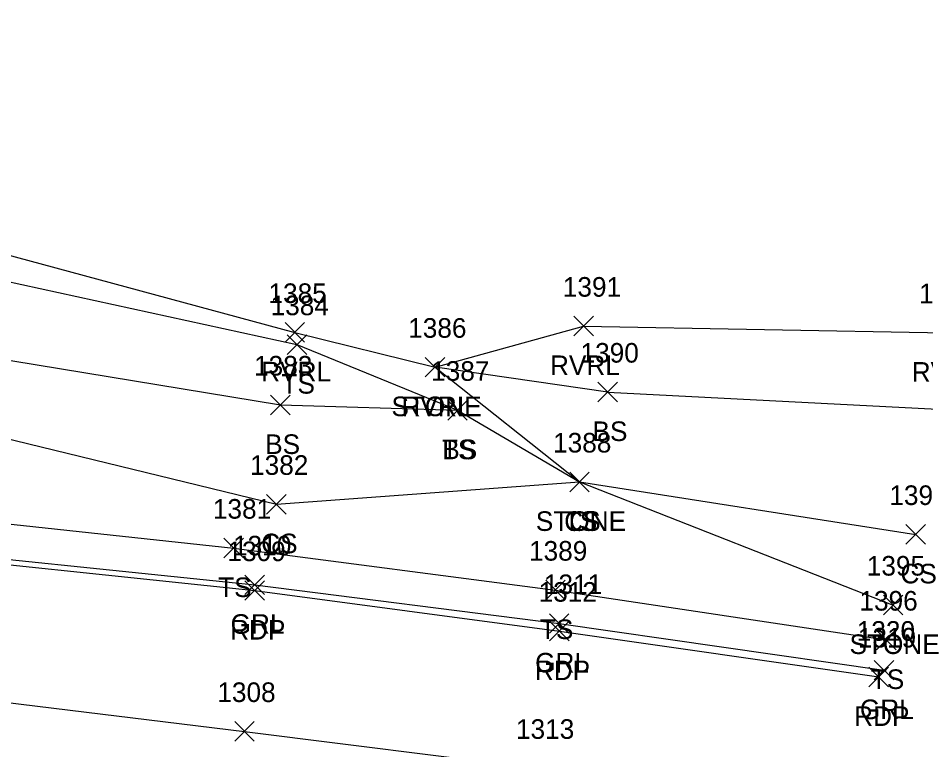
# Model space of a CAD drawing. Extents: x 1514253 to 1516033, y 782541 to 785002.
# Drawn here: x 1515367.9 to 1515460.6, y 782687.6 to 782762.3 of the extents above; entities that cross this region are included whole.
import ezdxf

# ---------------------------------------------------------------- set-up
doc = ezdxf.new("R2010")
doc.units = 0
for name, color, linetype in [('L_A', 7, 'Continuous'), ('L_I', 7, 'Continuous'), ('L_TIC', 7, 'Continuous'), ('LASF', 7, 'Continuous'), ('LAWE', 7, 'Continuous'), ('LELB', 7, 'Continuous'), ('P_A', 7, 'Continuous'), ('P_I', 7, 'Continuous'), ('P_TIC', 7, 'Continuous'), ('PET', 7, 'Continuous'), ('PRC', 7, 'Continuous'), ('R_A', 7, 'Continuous'), ('R_I', 7, 'Continuous'), ('R_TIC', 7, 'Continuous'), ('RGR', 7, 'Continuous')]:
    doc.layers.add(name, color=color, linetype=linetype)

msp = doc.modelspace()

# ---------------------------------------------------------------- linework, layer by layer
at = {"layer": 'L_TIC'}
for points in [[(1515395.169, 782729.21), (1515397.169, 782731.21)], [(1515397.169, 782729.21), (1515395.169, 782731.21)], [(1515424.647, 782729.856), (1515426.647, 782731.856)], [(1515426.647, 782729.856), (1515424.647, 782731.856)], [(1515395.387, 782727.965), (1515397.387, 782729.965)], [(1515397.387, 782727.965), (1515395.387, 782729.965)], [(1515409.484, 782725.666), (1515411.484, 782727.666)], [(1515411.484, 782725.666), (1515409.484, 782727.666)], [(1515409.484, 782725.666), (1515411.484, 782727.666)], [(1515411.484, 782725.666), (1515409.484, 782727.666)], [(1515427.11, 782723.129), (1515429.11, 782725.129)], [(1515429.11, 782723.129), (1515427.11, 782725.129)], [(1515393.696, 782721.81), (1515395.696, 782723.81)], [(1515395.696, 782721.81), (1515393.696, 782723.81)], [(1515411.772, 782721.272), (1515413.772, 782723.272)], [(1515413.772, 782721.272), (1515411.772, 782723.272)], [(1515411.772, 782721.272), (1515413.772, 782723.272)], [(1515413.772, 782721.272), (1515411.772, 782723.272)], [(1515424.22, 782713.959), (1515426.22, 782715.959)], [(1515426.22, 782713.959), (1515424.22, 782715.959)], [(1515424.22, 782713.959), (1515426.22, 782715.959)], [(1515426.22, 782713.959), (1515424.22, 782715.959)], [(1515424.22, 782713.959), (1515426.22, 782715.959)], [(1515426.22, 782713.959), (1515424.22, 782715.959)], [(1515393.291, 782711.678), (1515395.291, 782713.678)], [(1515395.291, 782711.678), (1515393.291, 782713.678)], [(1515458.543, 782708.604), (1515460.543, 782710.604)], [(1515460.543, 782708.604), (1515458.543, 782710.604)], [(1515388.927, 782707.211), (1515390.927, 782709.211)], [(1515390.927, 782707.211), (1515388.927, 782709.211)], [(1515421.772, 782702.928), (1515423.772, 782704.928)], [(1515423.772, 782702.928), (1515421.772, 782704.928)], [(1515456.239, 782701.402), (1515458.239, 782703.402)], [(1515458.239, 782701.402), (1515456.239, 782703.402)], [(1515455.544, 782697.832), (1515457.544, 782699.832)], [(1515457.544, 782697.832), (1515455.544, 782699.832)]]:
    msp.add_lwpolyline(points, dxfattribs=at)
at = {"layer": 'LASF'}
msp.add_lwpolyline([(1515410.484, 782726.666), (1515425.22, 782714.959), (1515457.239, 782702.402)], dxfattribs=at)
at = {"layer": 'LAWE'}
msp.add_lwpolyline([(1515202.172, 782762.269), (1515243.715, 782756.275), (1515286.282, 782747.113), (1515297.436, 782750.043), (1515300.761, 782752.518), (1515315.459, 782751.021), (1515328.638, 782746.746), (1515343.196, 782744.521), (1515396.169, 782730.21), (1515410.484, 782726.666), (1515425.647, 782730.856), (1515462.568, 782730.179)], dxfattribs=at)
at = {"layer": 'LELB'}
for points in [[(1515297.626, 782746.184), (1515301.912, 782746.264), (1515303.241, 782741.95), (1515307.469, 782738.508), (1515311.492, 782738.134), (1515315.133, 782736.763), (1515317.902, 782738.298), (1515317.8, 782745.406), (1515329.34, 782743.85), (1515353.31, 782738.376), (1515396.387, 782728.965), (1515412.772, 782722.272), (1515425.22, 782714.959)], [(1515201.947, 782733.368), (1515243.565, 782729.954), (1515286.67, 782732.441), (1515301.661, 782731.517), (1515315.516, 782732.446), (1515331.938, 782733.389), (1515354.734, 782729.396), (1515394.696, 782722.81), (1515412.772, 782722.272)], [(1515428.11, 782724.129), (1515410.484, 782726.666)], [(1515200.967, 782724.685), (1515243.492, 782722.774), (1515286.827, 782724.139), (1515305.143, 782723.876), (1515320.009, 782723.688), (1515332.817, 782725.68), (1515355.56, 782722.098), (1515394.291, 782712.678), (1515425.22, 782714.959), (1515459.543, 782709.604)], [(1515428.11, 782724.129), (1515463.097, 782722.297)], [(1515329.484, 782713.558), (1515354.865, 782711.959), (1515389.927, 782708.211), (1515422.772, 782703.928), (1515456.544, 782698.832)]]:
    msp.add_lwpolyline(points, dxfattribs=at)
at = {"layer": 'P_TIC'}
for points in [[(1515391.07, 782702.879), (1515393.07, 782704.879)], [(1515393.07, 782702.879), (1515391.07, 782704.879)], [(1515422.174, 782698.738), (1515424.174, 782700.738)], [(1515424.174, 782698.738), (1515422.174, 782700.738)], [(1515454.769, 782694.064), (1515456.769, 782696.064)], [(1515456.769, 782694.064), (1515454.769, 782696.064)], [(1515390.027, 782688.505), (1515392.027, 782690.505)], [(1515392.027, 782688.505), (1515390.027, 782690.505)]]:
    msp.add_lwpolyline(points, dxfattribs=at)
at = {"layer": 'PET'}
msp.add_lwpolyline([(1515198.602, 782712.943), (1515237.639, 782713.339), (1515272.199, 782712.403), (1515309.559, 782711.261), (1515351.19, 782708.158), (1515392.07, 782703.879), (1515423.174, 782699.738), (1515455.769, 782695.064)], dxfattribs=at)
at = {"layer": 'PRC'}
msp.add_lwpolyline([(1515198.294, 782698.445), (1515237.18, 782698.993), (1515272.827, 782698.875), (1515307.336, 782697.263), (1515350.128, 782694.483), (1515391.027, 782689.505), (1515420.865, 782685.748), (1515453.487, 782680.583)], dxfattribs=at)
at = {"layer": 'R_TIC'}
for points in [[(1515391.069, 782703.462), (1515393.069, 782705.462)], [(1515393.069, 782703.462), (1515391.069, 782705.462)], [(1515422.149, 782699.515), (1515424.149, 782701.515)], [(1515424.149, 782699.515), (1515422.149, 782701.515)], [(1515455.301, 782694.756), (1515457.301, 782696.756)], [(1515457.301, 782694.756), (1515455.301, 782696.756)]]:
    msp.add_lwpolyline(points, dxfattribs=at)
at = {"layer": 'RGR'}
msp.add_lwpolyline([(1515198.569, 782713.798), (1515237.597, 782714.039), (1515271.876, 782713.333), (1515309.648, 782711.931), (1515351.2, 782708.686), (1515392.069, 782704.462), (1515423.149, 782700.515), (1515456.301, 782695.756)], dxfattribs=at)

# ---------------------------------------------------------------- texts
at = {"layer": 'L_A'}
for s, p in [('RVRL', (1515422.214, 782725.856)), ('RVRL', (1515392.735, 782725.21)), ('RVRL', (1515459.135, 782725.179)), ('TS', (1515394.797, 782723.965)), ('STONE', (1515406.028, 782721.666)), ('RVRL', (1515407.051, 782721.666)), ('BS', (1515426.551, 782719.129)), ('BS', (1515393.137, 782717.81)), ('TS', (1515411.181, 782717.272)), ('BS', (1515411.213, 782717.272)), ('STONE', (1515420.763, 782709.959)), ('TS', (1515423.629, 782709.959)), ('CS', (1515423.661, 782709.959)), ('CS', (1515392.732, 782707.678)), ('CS', (1515457.984, 782704.604)), ('TS', (1515388.337, 782703.211)), ('TS', (1515421.182, 782698.928)), ('STONE', (1515452.782, 782697.402)), ('TS', (1515454.954, 782693.832))]:
    msp.add_text(s, height=2, dxfattribs=at).set_placement(p)
at = {"layer": 'L_I'}
for s, p in [('1391', (1515423.521, 782733.856)), ('1385', (1515393.476, 782733.21)), ('1392', (1515459.875, 782733.179)), ('1384', (1515393.694, 782731.965)), ('1386', (1515407.736, 782729.666)), ('1386', (1515407.736, 782729.666)), ('1390', (1515425.331, 782727.129)), ('1383', (1515392.003, 782725.81)), ('1387', (1515410.079, 782725.272)), ('1387', (1515410.079, 782725.272)), ('1388', (1515422.527, 782717.959)), ('1388', (1515422.527, 782717.959)), ('1388', (1515422.527, 782717.959)), ('1382', (1515391.598, 782715.678)), ('1394', (1515456.85, 782712.604)), ('1381', (1515387.801, 782711.211)), ('1389', (1515420.071, 782706.928)), ('1395', (1515454.546, 782705.402)), ('1396', (1515453.796, 782701.832))]:
    msp.add_text(s, height=2, dxfattribs=at).set_placement(p)
at = {"layer": 'P_A'}
for p in [(1515389.558, 782698.879), (1515420.662, 782694.738), (1515453.257, 782690.064)]:
    msp.add_text('RDP', height=2, dxfattribs=at).set_placement(p)
at = {"layer": 'P_I'}
for s, p in [('1309', (1515389.29, 782706.879)), ('1312', (1515421.048, 782702.738)), ('1319', (1515453.635, 782698.064)), ('1308', (1515388.256, 782692.505)), ('1313', (1515418.739, 782688.748))]:
    msp.add_text(s, height=2, dxfattribs=at).set_placement(p)
at = {"layer": 'R_A'}
for p in [(1515389.612, 782699.462), (1515420.693, 782695.515), (1515453.844, 782690.756)]:
    msp.add_text('GRL', height=2, dxfattribs=at).set_placement(p)
at = {"layer": 'R_I'}
for s, p in [('1310', (1515389.856, 782707.462)), ('1311', (1515421.59, 782703.515)), ('1320', (1515453.521, 782698.756))]:
    msp.add_text(s, height=2, dxfattribs=at).set_placement(p)

doc.saveas('drawing.dxf')
